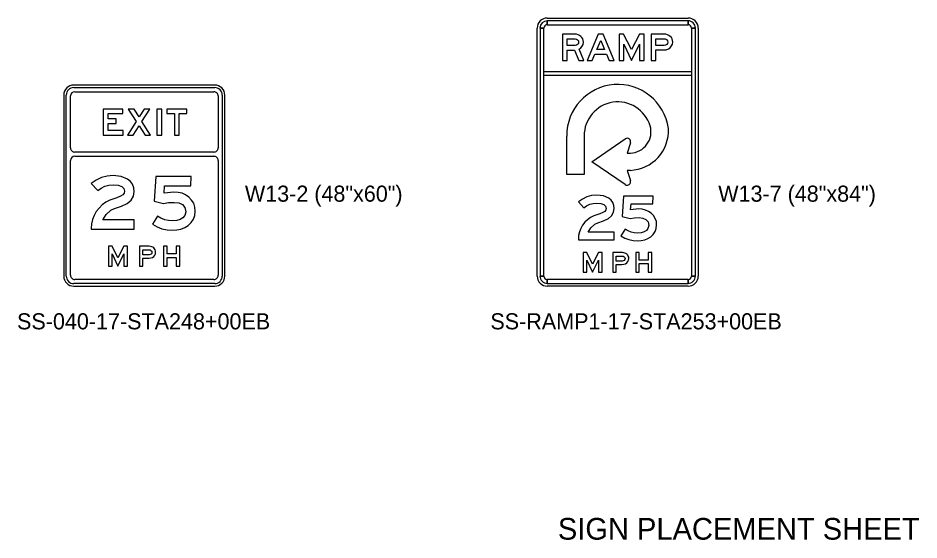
# Model space of a CAD drawing. Extents: x 620856.8 to 620948.6, y 415598.8 to 415658.2.
# Drawn here: x 620926.25 to 620948.63, y 415598.76 to 415611.74 of the extents above; entities that cross this region are included whole.
import ezdxf

# ---------------------------------------------------------------- set-up
doc = ezdxf.new("R2010")
doc.units = 0
doc.layers.add('G-ANNO-TEXT', color=7, linetype='Continuous')
doc.layers.add('SIGNS', color=7, linetype='Continuous')

msp = doc.modelspace()

# ---------------------------------------------------------------- linework, layer by layer
at = {"layer": 'SIGNS'}
for p, q in [((620939.395, 415611.742), (620942.895, 415611.742)), ((620939.395, 415611.575), (620939.395, 415611.673)), ((620942.895, 415611.673), (620942.895, 415611.575)), ((620939.145, 415605.325), (620939.145, 415611.492)), ((620939.215, 415611.492), (620939.312, 415611.492)), ((620942.979, 415611.492), (620943.076, 415611.492)), ((620943.145, 415611.492), (620943.145, 415605.325)), ((620931.133, 415610.075), (620927.633, 415610.075)), ((620931.133, 415610.075), (620927.633, 415610.075)), ((620927.633, 415610.013), (620931.133, 415610.013)), ((620931.133, 415610.075), (620931.133, 415610.075)), ((620931.133, 415610.075), (620931.133, 415610.075)), ((620927.383, 415609.825), (620927.383, 415609.825)), ((620927.383, 415609.825), (620927.383, 415609.825)), ((620927.383, 415609.825), (620927.383, 415605.325)), ((620927.383, 415609.825), (620927.383, 415605.325)), ((620927.446, 415605.325), (620927.446, 415609.825)), ((620927.55, 415608.513), (620927.55, 415609.804)), ((620927.654, 415609.909), (620931.113, 415609.909)), ((620931.217, 415609.804), (620931.217, 415608.513)), ((620931.321, 415609.825), (620931.321, 415605.325)), ((620931.383, 415605.325), (620931.383, 415609.825)), ((620931.383, 415605.325), (620931.383, 415609.825)), ((620939.88, 415607.855), (620939.88, 415608.806)), ((620940.313, 415608.806), (620940.312, 415607.855)), ((620940.506, 415608.169), (620941.334, 415608.74)), ((620941.463, 415608.639), (620941.379, 415608.385)), ((620931.113, 415608.409), (620927.654, 415608.409)), ((620927.654, 415608.409), (620927.654, 415608.409)), ((620927.654, 415608.409), (620927.654, 415608.409)), ((620941.379, 415608.385), (620941.461, 415608.385)), ((620927.55, 415605.346), (620927.55, 415608.2)), ((620927.654, 415608.304), (620931.113, 415608.304)), ((620931.217, 415608.2), (620931.217, 415605.346)), ((620941.334, 415607.599), (620940.506, 415608.169)), ((620941.459, 415607.953), (620941.379, 415607.953)), ((620941.379, 415607.953), (620941.463, 415607.699)), ((620940.312, 415607.855), (620939.88, 415607.855)), ((620931.113, 415605.242), (620927.654, 415605.242)), ((620927.654, 415605.242), (620927.654, 415605.242)), ((620927.654, 415605.242), (620927.654, 415605.242)), ((620931.383, 415605.325), (620931.383, 415605.325)), ((620931.383, 415605.325), (620931.383, 415605.325)), ((620939.312, 415605.325), (620939.215, 415605.325)), ((620939.395, 415605.145), (620939.395, 415605.242)), ((620942.895, 415605.242), (620942.895, 415605.145)), ((620943.076, 415605.325), (620942.979, 415605.325)), ((620931.133, 415605.138), (620927.633, 415605.138)), ((620927.633, 415605.075), (620927.633, 415605.075)), ((620927.633, 415605.075), (620927.633, 415605.075)), ((620927.633, 415605.075), (620931.133, 415605.075)), ((620927.633, 415605.075), (620931.133, 415605.075)), ((620942.895, 415605.075), (620939.395, 415605.075))]:
    msp.add_line(p, q, dxfattribs=at)
for points in [[(620942.895, 415611.673), (620939.395, 415611.673), (620939.395, 415611.575), (620942.895, 415611.575), (620942.895, 415611.673), (620942.895, 415611.673)], [(620939.215, 415611.492), (620939.215, 415605.325), (620939.312, 415605.325), (620939.312, 415611.492), (620939.215, 415611.492), (620939.215, 415611.492)], [(620941.179, 415610.686), (620941.294, 415610.686), (620941.294, 415611.089), (620941.487, 415610.686), (620941.683, 415611.089), (620941.683, 415610.686), (620941.799, 415610.686), (620941.799, 415611.34), (620941.683, 415611.34), (620941.487, 415610.955), (620941.293, 415611.34), (620941.179, 415611.34)], [(620943.076, 415605.325), (620943.076, 415611.492), (620942.979, 415611.492), (620942.979, 415605.325), (620943.076, 415605.325), (620943.076, 415605.325)], [(620942.979, 415610.311), (620939.312, 415610.311), (620939.312, 415610.409), (620942.979, 415610.409), (620942.979, 415610.311), (620942.979, 415610.311)], [(620928.363, 415608.825), (620928.857, 415608.825), (620928.857, 415608.941), (620928.482, 415608.941), (620928.482, 415609.12), (620928.681, 415609.12), (620928.681, 415609.236), (620928.482, 415609.236), (620928.482, 415609.364), (620928.846, 415609.364), (620928.846, 415609.479), (620928.363, 415609.479)], [(620928.968, 415608.825), (620929.107, 415608.825), (620929.253, 415609.061), (620929.402, 415608.825), (620929.541, 415608.825), (620929.325, 415609.17), (620929.52, 415609.479), (620929.378, 415609.479), (620929.253, 415609.284), (620929.128, 415609.479), (620928.986, 415609.479), (620929.183, 415609.17)], [(620929.698, 415608.825), (620929.817, 415608.825), (620929.817, 415609.479), (620929.698, 415609.479)], [(620930.134, 415608.825), (620930.25, 415608.825), (620930.25, 415609.369), (620930.44, 415609.369), (620930.44, 415609.479), (620929.946, 415609.479), (620929.946, 415609.369), (620930.134, 415609.369)], [(620928.063, 415606.492), (620929.131, 415606.492), (620929.131, 415606.724), (620928.352, 415606.724), (620928.436, 415606.857), (620928.551, 415606.961), (620928.645, 415607.005), (620928.815, 415607.064), (620928.958, 415607.127), (620929.055, 415607.211), (620929.112, 415607.315), (620929.131, 415607.427), (620929.121, 415607.523), (620929.091, 415607.607), (620929.04, 415607.679), (620928.969, 415607.737), (620928.811, 415607.803), (620928.613, 415607.825), (620928.459, 415607.812), (620928.316, 415607.775), (620928.184, 415607.713), (620928.063, 415607.626), (620928.225, 415607.451), (620928.308, 415607.512), (620928.401, 415607.557), (620928.503, 415607.584), (620928.616, 415607.593), (620928.738, 415607.583), (620928.825, 415607.553), (620928.878, 415607.503), (620928.895, 415607.433), (620928.884, 415607.386), (620928.85, 415607.344), (620928.795, 415607.31), (620928.699, 415607.274), (620928.528, 415607.214), (620928.427, 415607.16), (620928.338, 415607.094), (620928.259, 415607.018), (620928.191, 415606.931), (620928.134, 415606.832), (620928.094, 415606.729), (620928.07, 415606.622), (620928.063, 415606.511)], [(620929.583, 415606.614), (620929.7, 415606.549), (620929.822, 415606.503), (620929.949, 415606.476), (620930.08, 415606.466), (620930.191, 415606.474), (620930.294, 415606.496), (620930.388, 415606.532), (620930.473, 415606.583), (620930.551, 415606.655), (620930.607, 415606.738), (620930.64, 415606.832), (620930.651, 415606.939), (620930.641, 415607.042), (620930.611, 415607.135), (620930.56, 415607.217), (620930.49, 415607.29), (620930.41, 415607.344), (620930.321, 415607.384), (620930.223, 415607.407), (620930.117, 415607.415), (620929.875, 415607.39), (620929.889, 415607.569), (620930.542, 415607.569), (620930.547, 415607.8), (620929.667, 415607.8), (620929.625, 415607.19), (620929.861, 415607.13), (620929.987, 415607.151), (620930.126, 415607.159), (620930.24, 415607.144), (620930.33, 415607.103), (620930.394, 415607.027), (620930.415, 415606.922), (620930.39, 415606.832), (620930.344, 415606.773), (620930.277, 415606.731), (620930.188, 415606.705), (620930.078, 415606.697), (620929.983, 415606.704), (620929.89, 415606.726), (620929.798, 415606.763), (620929.709, 415606.815)], [(620940.168, 415606.225), (620941.058, 415606.225), (620941.058, 415606.418), (620940.408, 415606.418), (620940.478, 415606.529), (620940.574, 415606.616), (620940.652, 415606.653), (620940.794, 415606.702), (620940.914, 415606.754), (620940.994, 415606.824), (620941.042, 415606.911), (620941.058, 415607.004), (620941.049, 415607.084), (620941.024, 415607.154), (620940.981, 415607.214), (620940.922, 415607.262), (620940.791, 415607.317), (620940.626, 415607.336), (620940.497, 415607.325), (620940.378, 415607.294), (620940.268, 415607.242), (620940.168, 415607.17), (620940.303, 415607.023), (620940.372, 415607.075), (620940.449, 415607.112), (620940.534, 415607.134), (620940.628, 415607.142), (620940.73, 415607.134), (620940.803, 415607.109), (620940.846, 415607.067), (620940.861, 415607.009), (620940.852, 415606.97), (620940.824, 415606.934), (620940.778, 415606.906), (620940.697, 415606.876), (620940.554, 415606.827), (620940.471, 415606.781), (620940.396, 415606.727), (620940.331, 415606.663), (620940.274, 415606.59), (620940.226, 415606.508), (620940.193, 415606.422), (620940.173, 415606.333), (620940.168, 415606.241)], [(620941.223, 415606.326), (620941.321, 415606.272), (620941.422, 415606.234), (620941.528, 415606.211), (620941.637, 415606.203), (620941.73, 415606.209), (620941.816, 415606.228), (620941.894, 415606.258), (620941.965, 415606.301), (620942.03, 415606.36), (620942.076, 415606.43), (620942.104, 415606.508), (620942.113, 415606.597), (620942.105, 415606.683), (620942.079, 415606.761), (620942.037, 415606.829), (620941.979, 415606.89), (620941.912, 415606.935), (620941.838, 415606.968), (620941.757, 415606.987), (620941.668, 415606.994), (620941.466, 415606.973), (620941.478, 415607.122), (620942.022, 415607.122), (620942.026, 415607.314), (620941.293, 415607.314), (620941.258, 415606.806), (620941.455, 415606.756), (620941.56, 415606.774), (620941.676, 415606.78), (620941.771, 415606.768), (620941.845, 415606.734), (620941.899, 415606.671), (620941.917, 415606.583), (620941.896, 415606.508), (620941.857, 415606.459), (620941.801, 415606.424), (620941.727, 415606.403), (620941.635, 415606.396), (620941.556, 415606.401), (620941.479, 415606.42), (620941.402, 415606.451), (620941.328, 415606.494)], [(620928.498, 415605.575), (620928.584, 415605.575), (620928.584, 415605.877), (620928.729, 415605.575), (620928.876, 415605.877), (620928.876, 415605.575), (620928.963, 415605.575), (620928.963, 415606.066), (620928.876, 415606.066), (620928.729, 415605.777), (620928.583, 415606.066), (620928.498, 415606.066)], [(620929.864, 415605.575), (620929.95, 415605.575), (620929.95, 415605.791), (620930.171, 415605.791), (620930.171, 415605.575), (620930.264, 415605.575), (620930.264, 415606.066), (620930.171, 415606.066), (620930.171, 415605.879), (620929.95, 415605.879), (620929.95, 415606.066), (620929.864, 415606.066)], [(620940.29, 415605.419), (620940.377, 415605.419), (620940.377, 415605.721), (620940.521, 415605.419), (620940.668, 415605.721), (620940.668, 415605.419), (620940.755, 415605.419), (620940.755, 415605.909), (620940.668, 415605.909), (620940.521, 415605.62), (620940.376, 415605.909), (620940.29, 415605.909)], [(620941.596, 415605.419), (620941.682, 415605.419), (620941.682, 415605.635), (620941.903, 415605.635), (620941.903, 415605.419), (620941.996, 415605.419), (620941.996, 415605.909), (620941.903, 415605.909), (620941.903, 415605.723), (620941.682, 415605.723), (620941.682, 415605.909), (620941.596, 415605.909)], [(620939.395, 415605.145), (620942.895, 415605.145), (620942.895, 415605.242), (620939.395, 415605.242), (620939.395, 415605.145), (620939.395, 415605.145)]]:
    msp.add_lwpolyline(points, close=True, dxfattribs=at)
for points in [[(620939.771, 415610.686), (620939.887, 415610.686), (620939.887, 415610.946), (620940.072, 415610.946), (620940.182, 415610.686), (620940.305, 415610.686), (620940.185, 415610.966), (620940.229, 415610.997), (620940.263, 415611.039), (620940.284, 415611.087), (620940.292, 415611.14), (620940.288, 415611.182), (620940.275, 415611.22), (620940.255, 415611.255), (620940.228, 415611.285), (620940.195, 415611.309), (620940.159, 415611.326), (620940.12, 415611.337), (620940.077, 415611.34), (620939.771, 415611.34), (620939.771, 415610.686)], [(620940.385, 415610.686), (620940.514, 415610.686), (620940.579, 415610.841), (620940.866, 415610.841), (620940.93, 415610.686), (620941.057, 415610.686), (620940.783, 415611.34), (620940.662, 415611.34), (620940.385, 415610.686)], [(620941.98, 415610.686), (620942.095, 415610.686), (620942.095, 415610.947), (620942.286, 415610.947), (620942.35, 415610.953), (620942.405, 415610.972), (620942.45, 415611.002), (620942.485, 415611.046), (620942.506, 415611.094), (620942.514, 415611.144), (620942.51, 415611.185), (620942.498, 415611.222), (620942.479, 415611.255), (620942.452, 415611.285), (620942.419, 415611.309), (620942.383, 415611.326), (620942.344, 415611.337), (620942.301, 415611.34), (620941.98, 415611.34), (620941.98, 415610.686)], [(620939.887, 415611.058), (620939.887, 415611.225), (620940.087, 415611.225), (620940.12, 415611.219), (620940.149, 415611.201), (620940.167, 415611.174), (620940.174, 415611.14), (620940.167, 415611.108), (620940.147, 415611.081), (620940.119, 415611.064), (620940.085, 415611.058), (620939.887, 415611.058)], [(620940.63, 415610.959), (620940.722, 415611.182), (620940.815, 415610.959), (620940.63, 415610.959)], [(620942.095, 415611.058), (620942.095, 415611.225), (620942.289, 415611.225), (620942.328, 415611.22), (620942.359, 415611.204), (620942.382, 415611.176), (620942.39, 415611.14), (620942.383, 415611.107), (620942.362, 415611.081), (620942.331, 415611.064), (620942.296, 415611.058), (620942.095, 415611.058)], [(620929.265, 415605.575), (620929.351, 415605.575), (620929.351, 415605.771), (620929.494, 415605.771), (620929.543, 415605.776), (620929.584, 415605.789), (620929.618, 415605.812), (620929.644, 415605.845), (620929.66, 415605.881), (620929.665, 415605.918), (620929.662, 415605.949), (620929.654, 415605.977), (620929.639, 415606.002), (620929.619, 415606.024), (620929.594, 415606.042), (620929.567, 415606.055), (620929.538, 415606.063), (620929.505, 415606.066), (620929.265, 415606.066), (620929.265, 415605.575)], [(620929.351, 415605.854), (620929.351, 415605.979), (620929.497, 415605.979), (620929.526, 415605.975), (620929.549, 415605.963), (620929.567, 415605.943), (620929.572, 415605.916), (620929.567, 415605.891), (620929.551, 415605.871), (620929.529, 415605.858), (620929.502, 415605.854), (620929.351, 415605.854)], [(620941.021, 415605.419), (620941.107, 415605.419), (620941.107, 415605.615), (620941.25, 415605.615), (620941.299, 415605.619), (620941.34, 415605.633), (620941.373, 415605.656), (620941.399, 415605.688), (620941.416, 415605.725), (620941.421, 415605.762), (620941.418, 415605.793), (620941.409, 415605.821), (620941.395, 415605.846), (620941.375, 415605.868), (620941.35, 415605.886), (620941.323, 415605.899), (620941.294, 415605.907), (620941.261, 415605.909), (620941.021, 415605.909), (620941.021, 415605.419)], [(620941.107, 415605.698), (620941.107, 415605.823), (620941.253, 415605.823), (620941.282, 415605.819), (620941.305, 415605.807), (620941.322, 415605.786), (620941.328, 415605.76), (620941.323, 415605.735), (620941.307, 415605.715), (620941.284, 415605.702), (620941.258, 415605.698), (620941.107, 415605.698)]]:
    msp.add_lwpolyline(points, dxfattribs=at)
for centre, radius, start, end in [((620939.395, 415611.492), 0.25, 90.0002, 179.9998), ((620942.895, 415611.492), 0.25, 360, 90.0002), ((620939.395, 415611.492), 0.181, 90.0002, 179.9998), ((620939.395, 415611.492), 0.0833, 90.0002, 179.9998), ((620942.895, 415611.492), 0.181, 360, 90.0002), ((620942.895, 415611.492), 0.0833, 360, 90.0002), ((620927.633, 415609.825), 0.25, 90.0002, 179.9998), ((620927.633, 415609.825), 0.25, 90.0002, 179.9998), ((620927.633, 415609.825), 0.187, 90.0002, 179.9998), ((620931.133, 415609.825), 0.25, 0, 90.0002), ((620931.133, 415609.825), 0.25, 0, 90.0002), ((620931.133, 415609.825), 0.187, 0, 90.0002), ((620941.149, 415608.82), 1.269, 7.9809, 180.6513), ((620927.654, 415609.804), 0.104, 90.0002, 179.9998), ((620931.113, 415609.804), 0.104, 0, 90.0002), ((620941.149, 415608.82), 0.836, 16.6024, 180.9355), ((620941.447, 415608.91), 0.525, 271.5241, 16.4797), ((620941.417, 415608.943), 0.99, 272.4615, 3.0748), ((620941.436, 415608.954), 0.976, 2.5524, 2.6462), ((620941.149, 415608.821), 0.837, 181.006, 181.0329), ((620941.149, 415608.821), 0.837, 181.0329, 181.0507), ((620941.38, 415608.666), 0.0864, 341.802, 122.1956), ((620927.654, 415608.513), 0.104, 179.9998, 270.0001), ((620931.113, 415608.513), 0.104, 270.0001, 0.0003), ((620942.581, 415609.166), 1.365, 214.8815, 214.8918), ((620927.654, 415608.2), 0.104, 90.0002, 179.9998), ((620931.113, 415608.2), 0.104, 0, 90.0002), ((620941.38, 415607.672), 0.0864, 237.8044, 18.198), ((620927.633, 415605.325), 0.25, 179.9998, 270.0001), ((620927.633, 415605.325), 0.25, 179.9998, 270.0001), ((620927.633, 415605.325), 0.187, 179.9998, 270.0001), ((620927.654, 415605.346), 0.104, 179.9998, 270.0001), ((620931.113, 415605.346), 0.104, 270.0001, 0.0003), ((620931.133, 415605.325), 0.25, 270.0001, 0.0003), ((620931.133, 415605.325), 0.25, 270.0001, 0.0003), ((620931.133, 415605.325), 0.187, 270.0001, 0.0003), ((620939.395, 415605.325), 0.25, 179.9998, 270.0001), ((620939.395, 415605.325), 0.181, 179.9998, 270.0001), ((620939.395, 415605.325), 0.0833, 179.9998, 270.0001), ((620942.895, 415605.325), 0.181, 270.0001, 0.0003), ((620942.895, 415605.325), 0.0833, 270.0001, 0.0003), ((620942.895, 415605.325), 0.25, 270.0001, 0.0003)]:
    msp.add_arc(centre, radius, start, end, dxfattribs=at)

# ---------------------------------------------------------------- texts
at = {"layer": 'G-ANNO-TEXT'}
msp.add_text('SIGN PLACEMENT SHEET', height=0.54, dxfattribs=at).set_placement((620939.659, 415598.772))
at = {"layer": 'SIGNS'}
for s, p in [('W13-2 (48"x60")', (620931.883, 415607.175)), ('W13-7 (48"x84")', (620943.643, 415607.175)), ('SS-040-17-STA248+00EB', (620926.222, 415604.001)), ('SS-RAMP1-17-STA253+00EB', (620937.982, 415604.001))]:
    msp.add_text(s, height=0.4, rotation=0, dxfattribs=at).set_placement(p)

doc.saveas('drawing.dxf')
